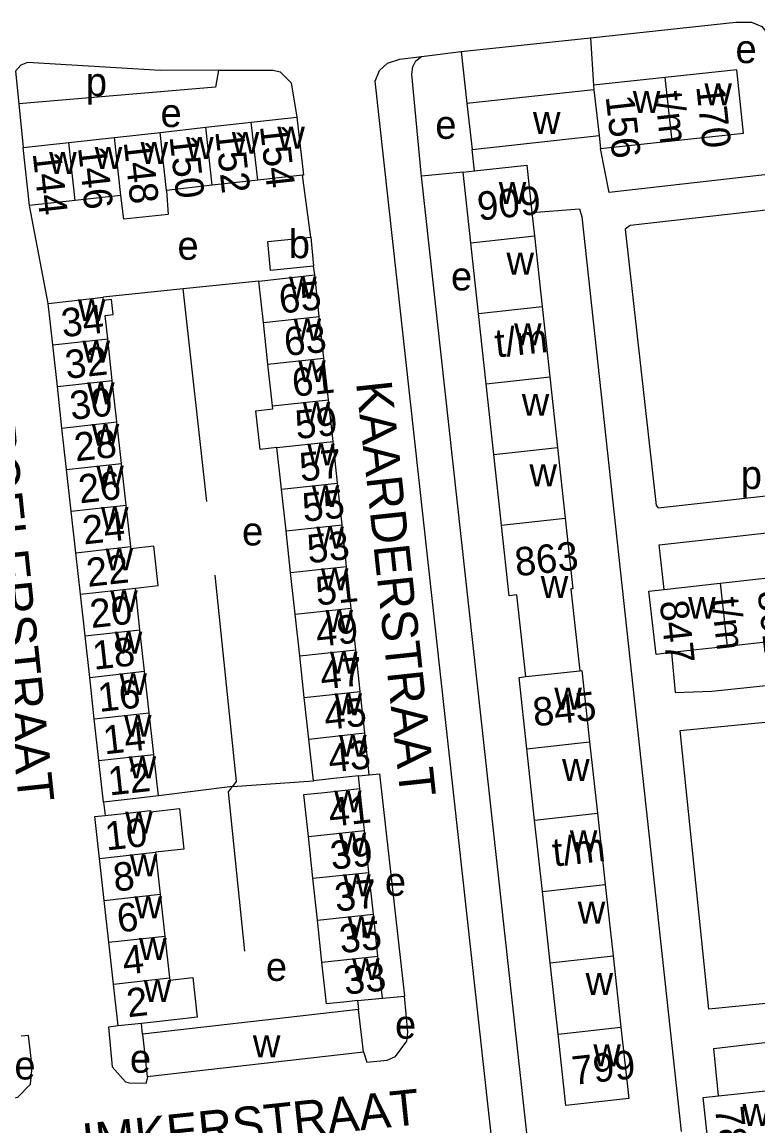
# Model space of a CAD drawing. Extents: x 159294 to 161936, y 384538 to 386517.
# Drawn here: x 161110.6 to 161214, y 385080.5 to 385235.4 of the extents above; entities that cross this region are included whole.
import ezdxf

# ---------------------------------------------------------------- set-up
doc = ezdxf.new("R2010")
doc.units = 0
for name, color, linetype in [('BLT_Basislijn', 7, 'Continuous'), ('BLT_Bebouwing', 7, 'Continuous'), ('BLT_Centroide', 7, 'Continuous'), ('BLT_Huisnummer', 7, 'Continuous'), ('BLT_Huisnummer_ tussenligend', 7, 'Continuous'), ('BLT_Huisnummer_reeks', 7, 'Continuous'), ('BLT_Onderverdeling_panden', 7, 'Continuous'), ('BLT_Straatnaam', 7, 'Continuous')]:
    doc.layers.add(name, color=color, linetype=linetype)

msp = doc.modelspace()

# ---------------------------------------------------------------- linework, layer by layer
at = {"layer": 'BLT_Basislijn'}
for p, q in [((161172.28, 385231.27), (161190.46, 385233.23)), ((161190.46, 385233.23), (161190.87, 385226.57)), ((161166.75, 385230.6), (161172.28, 385231.27)), ((161172.28, 385231.27), (161173.11, 385223.99)), ((161110.16, 385223.96), (161110.78, 385217.81)), ((161174.16, 385214.52), (161173.82, 385217.55)), ((161151.18, 385205.21), (161150.03, 385213.92)), ((161172.59, 385214.35), (161166.72, 385213.81)), ((161181.76, 385077.34), (161166.72, 385213.81)), ((161114.29, 385195.93), (161111.69, 385209.67)), ((161151.74, 385199.93), (161151.57, 385201.15)), ((161143.88, 385199.07), (161133.26, 385197.97)), ((161133.26, 385197.97), (161122.01, 385196.79)), ((161136.56, 385168.1), (161133.26, 385197.97)), ((161140.17, 385128.11), (161151.54, 385128.91)), ((161158.07, 385127.82), (161157.89, 385129.61)), ((161140.17, 385128.11), (161129.79, 385126.78)), ((161122.07, 385125.92), (161122.29, 385124.04)), ((161157.76, 385098.05), (161157.89, 385096.79)), ((161161.23, 385098.42), (161164.32, 385098.67)), ((161127.54, 385093.35), (161127.41, 385094.85))]:
    msp.add_line(p, q, dxfattribs=at)
for points in [[(161190.46, 385233.23), (161210.86, 385235.41), (161213.05, 385235.42), (161214.5, 385234.81), (161216.25, 385232.63)], [(161176.79, 385076.79), (161160.22, 385227.14), (161160.83, 385228.63), (161161.96, 385229.64), (161163.67, 385230.2), (161166.75, 385230.6)], [(161166.72, 385213.81), (161166.67, 385214.22), (161165.38, 385228.11), (161165.51, 385229.14), (161165.94, 385229.97), (161166.75, 385230.6)], [(161138.23, 385228.66), (161130.06, 385228.63), (161111.39, 385229.74), (161110.47, 385229.39), (161109.7, 385228.53), (161110.16, 385223.96)], [(161138.23, 385228.66), (161137.82, 385226.3), (161110.16, 385223.96)], [(161138.23, 385228.66), (161145.88, 385228.67), (161146.89, 385228.42), (161148.41, 385226.88), (161149.24, 385222.08)], [(161218.23, 385214.36), (161193.1, 385211.51), (161191.86, 385217.67)], [(161182.23, 385208.7), (161188.91, 385209.22), (161189.26, 385208.08), (161203.21, 385079.69)], [(161218.81, 385209.42), (161196.05, 385206.87), (161195.35, 385206.33), (161199.66, 385167.55), (161199.98, 385167.23), (161223.09, 385169.82)], [(161200.79, 385155.78), (161200.12, 385162.03), (161223.63, 385164.64)], [(161137.69, 385157.8), (161140.72, 385128.82), (161140.17, 385128.11)], [(161201.83, 385146.9), (161202.35, 385141.29), (161207.48, 385141.49), (161225.87, 385143.43)], [(161230.63, 385099.17), (161207.1, 385096.83), (161203.06, 385135.98), (161226.44, 385138.28)], [(161159.4, 385129.77), (161160.82, 385129.91), (161164.28, 385099.09), (161164.32, 385098.67)], [(161141.9, 385104.99), (161139.62, 385127.37), (161140.17, 385128.11)], [(161158.56, 385090.85), (161159.05, 385089.39), (161161.92, 385089.68), (161163.07, 385090.22), (161164.66, 385092.36), (161164.82, 385093.64), (161164.32, 385098.67)], [(161124.11, 385094.49), (161122.76, 385094.34), (161123.29, 385088.78), (161125.14, 385086.65), (161125.7, 385086.49), (161128.04, 385086.46), (161128.31, 385087.29), (161128.21, 385087.41)], [(161107.73, 385085.33), (161108.03, 385084.13), (161110.02, 385084.49), (161111.84, 385086.31), (161112.06, 385088.75), (161111.54, 385093.17), (161110.49, 385093.04)], [(161208.43, 385084.68), (161207.76, 385091.33), (161231.18, 385094.08)]]:
    msp.add_lwpolyline(points, dxfattribs=at)
at = {"layer": 'BLT_Bebouwing'}
for p, q in [((161200.95, 385227.65), (161190.87, 385226.57)), ((161190.94, 385225.92), (161173.11, 385223.99)), ((161190.87, 385226.57), (161190.94, 385225.92)), ((161173.11, 385223.99), (161173.82, 385217.55)), ((161136.42, 385220.65), (161142.83, 385221.36)), ((161142.83, 385221.36), (161149.24, 385222.08)), ((161123.6, 385219.23), (161130.01, 385219.94)), ((161130.01, 385219.94), (161136.42, 385220.65)), ((161110.78, 385217.81), (161117.19, 385218.52)), ((161117.19, 385218.52), (161123.6, 385219.23)), ((161173.82, 385217.55), (161191.66, 385219.48)), ((161191.66, 385219.48), (161191.86, 385217.67)), ((161191.86, 385217.67), (161201.91, 385218.76)), ((161111.69, 385209.67), (161110.78, 385217.81)), ((161150.03, 385213.92), (161143.74, 385213.22)), ((161172.59, 385214.35), (161174.16, 385214.52)), ((161173.66, 385204.44), (161172.59, 385214.35)), ((161137.33, 385212.51), (161130.92, 385211.8)), ((161143.74, 385213.22), (161137.33, 385212.51)), ((161124.51, 385211.09), (161118.1, 385210.38)), ((161118.1, 385210.38), (161111.69, 385209.67)), ((161182.23, 385208.7), (161182.58, 385205.41)), ((161151.18, 385205.21), (161151.57, 385201.15)), ((161174.74, 385194.53), (161173.66, 385204.44)), ((161182.58, 385205.41), (161183.66, 385195.5)), ((161152.38, 385194.09), (161151.74, 385199.93)), ((161144.52, 385193.23), (161143.88, 385199.07)), ((161114.94, 385190.1), (161114.29, 385195.93)), ((161183.66, 385195.5), (161184.74, 385185.6)), ((161153.02, 385188.24), (161152.38, 385194.09)), ((161175.82, 385184.63), (161174.74, 385194.53)), ((161145.16, 385187.38), (161144.52, 385193.23)), ((161123.31, 385185.12), (161122.66, 385190.96)), ((161115.59, 385184.26), (161114.94, 385190.1)), ((161145.8, 385181.54), (161145.16, 385187.38)), ((161153.66, 385182.39), (161153.02, 385188.24)), ((161116.24, 385178.43), (161115.59, 385184.26)), ((161123.95, 385179.29), (161123.31, 385185.12)), ((161176.9, 385174.72), (161175.82, 385184.63)), ((161184.74, 385185.6), (161185.81, 385175.69)), ((161154.3, 385176.55), (161153.66, 385182.39)), ((161116.89, 385172.6), (161116.24, 385178.43)), ((161124.6, 385173.45), (161123.95, 385179.29)), ((161154.93, 385170.7), (161154.3, 385176.55)), ((161147.07, 385169.84), (161146.43, 385175.69)), ((161185.81, 385175.69), (161186.89, 385165.78)), ((161125.25, 385167.62), (161124.6, 385173.45)), ((161177.98, 385164.81), (161176.9, 385174.72)), ((161117.53, 385166.76), (161116.89, 385172.6)), ((161155.57, 385164.86), (161154.93, 385170.7)), ((161147.71, 385164), (161147.07, 385169.84)), ((161125.9, 385161.79), (161125.25, 385167.62)), ((161118.18, 385160.93), (161117.53, 385166.76)), ((161148.35, 385158.15), (161147.71, 385164)), ((161156.21, 385159.01), (161155.57, 385164.86)), ((161118.83, 385155.09), (161118.18, 385160.93)), ((161148.99, 385152.3), (161148.35, 385158.15)), ((161156.85, 385153.16), (161156.21, 385159.01)), ((161200.79, 385155.78), (161208.68, 385156.67)), ((161119.48, 385149.26), (161118.83, 385155.09)), ((161127.19, 385150.12), (161126.55, 385155.95)), ((161181.37, 385143.53), (161180.11, 385155.02)), ((161187.72, 385155.84), (161187.69, 385155.83)), ((161187.69, 385155.83), (161188.97, 385144.36)), ((161157.49, 385147.32), (161156.85, 385153.16)), ((161149.62, 385146.46), (161148.99, 385152.3)), ((161127.84, 385144.28), (161127.19, 385150.12)), ((161120.13, 385143.43), (161119.48, 385149.26)), ((161158.12, 385141.47), (161157.49, 385147.32)), ((161209.67, 385147.78), (161201.83, 385146.9)), ((161150.26, 385140.61), (161149.62, 385146.46)), ((161128.49, 385138.45), (161127.84, 385144.28)), ((161189.23, 385144.39), (161190.33, 385134.38)), ((161120.77, 385137.59), (161120.13, 385143.43)), ((161158.76, 385135.63), (161158.12, 385141.47)), ((161150.9, 385134.77), (161150.26, 385140.61)), ((161121.42, 385131.76), (161120.77, 385137.59)), ((161129.14, 385132.61), (161128.49, 385138.45)), ((161151.54, 385128.91), (161150.9, 385134.77)), ((161159.4, 385129.77), (161158.76, 385135.63)), ((161182.61, 385123.4), (161181.51, 385133.41)), ((161190.33, 385134.38), (161191.42, 385124.37)), ((161122.07, 385125.92), (161121.42, 385131.76)), ((161129.79, 385126.78), (161129.14, 385132.61)), ((161157.89, 385129.61), (161159.4, 385129.77)), ((161158.7, 385121.94), (161158.07, 385127.82)), ((161191.42, 385124.37), (161192.52, 385114.35)), ((161183.71, 385113.39), (161182.61, 385123.4)), ((161151.47, 385115.22), (161150.84, 385121.09)), ((161159.34, 385116.06), (161158.7, 385121.94)), ((161122.16, 385112.12), (161121.51, 385118)), ((161129.39, 385118.87), (161130.04, 385112.99)), ((161159.97, 385110.18), (161159.34, 385116.06)), ((161152.1, 385109.34), (161151.47, 385115.22)), ((161192.52, 385114.35), (161193.62, 385104.34)), ((161130.04, 385112.99), (161130.69, 385107.12)), ((161184.81, 385103.37), (161183.71, 385113.39)), ((161122.81, 385106.25), (161122.16, 385112.12)), ((161160.6, 385104.3), (161159.97, 385110.18)), ((161152.73, 385103.46), (161152.1, 385109.34)), ((161130.69, 385107.12), (161131.34, 385101.24)), ((161123.46, 385100.37), (161122.81, 385106.25)), ((161161.23, 385098.42), (161160.6, 385104.3)), ((161193.62, 385104.34), (161194.72, 385094.33)), ((161185.91, 385093.36), (161184.81, 385103.37)), ((161124.11, 385094.49), (161123.46, 385100.37)), ((161157.76, 385098.05), (161161.23, 385098.42)), ((161157.89, 385096.79), (161127.54, 385093.35)), ((161158.56, 385090.85), (161157.89, 385096.79)), ((161127.41, 385094.85), (161124.11, 385094.49)), ((161127.54, 385093.35), (161128.21, 385087.41)), ((161128.21, 385087.41), (161158.56, 385090.85)), ((161208.43, 385084.68), (161216.36, 385085.55))]:
    msp.add_line(p, q, dxfattribs=at)
for points in [[(161201.91, 385218.76), (161211.96, 385219.84), (161211, 385228.74), (161200.95, 385227.65)], [(161149.24, 385222.08), (161150.14, 385213.93), (161150.03, 385213.92)], [(161174.16, 385214.52), (161181.51, 385215.33), (161182.23, 385208.7)], [(161130.92, 385211.8), (161131.15, 385208.43), (161124.93, 385207.74), (161124.51, 385211.09)], [(161151.57, 385201.15), (161145.54, 385200.56), (161145.14, 385204.63), (161151.18, 385205.21)], [(161143.88, 385199.07), (161146.77, 385199.39), (161151.74, 385199.93)], [(161114.29, 385195.93), (161119.26, 385196.48), (161122.01, 385196.79)], [(161122.66, 385190.96), (161122.29, 385194.23), (161123.43, 385194.36), (161123.19, 385196.48), (161122.06, 385196.35), (161122.01, 385196.79)], [(161146.43, 385175.69), (161144.07, 385175.41), (161143.47, 385180.86), (161145.84, 385181.11), (161145.8, 385181.54)], [(161186.89, 385165.78), (161187.99, 385155.87), (161187.72, 385155.84)], [(161180.11, 385155.02), (161179.06, 385154.9), (161177.98, 385164.81)], [(161126.55, 385155.95), (161129.76, 385156.34), (161129.15, 385161.83), (161125.93, 385161.47), (161125.9, 385161.79)], [(161208.68, 385156.67), (161218.69, 385157.79), (161219.68, 385148.9), (161209.67, 385147.78)], [(161201.83, 385146.9), (161199.66, 385146.66), (161198.67, 385155.54), (161200.79, 385155.78)], [(161188.97, 385144.36), (161189.23, 385144.39), (161189.23, 385144.39)], [(161181.51, 385133.41), (161180.42, 385143.43), (161181.37, 385143.53)], [(161157.89, 385129.61), (161154.43, 385129.23), (161151.54, 385128.91)], [(161129.79, 385126.78), (161127.04, 385126.48), (161122.07, 385125.92)], [(161150.84, 385121.09), (161150.21, 385126.97), (161153.1, 385127.28), (161158.07, 385127.82)], [(161121.51, 385118), (161120.86, 385123.88), (161122.29, 385124.04)], [(161122.29, 385124.04), (161125.83, 385124.43), (161128.67, 385124.74), (161128.69, 385124.55), (161132.74, 385125), (161133.03, 385122.36), (161133.36, 385119.31), (161129.39, 385118.87)], [(161157.76, 385098.05), (161156.26, 385097.89), (161153.37, 385097.58), (161152.73, 385103.46)], [(161131.34, 385101.24), (161131.37, 385100.92), (161134.62, 385101.28), (161135.24, 385095.72), (161131.99, 385095.36), (161129.08, 385095.04), (161127.41, 385094.85)], [(161194.72, 385094.33), (161195.82, 385084.31), (161187.01, 385083.35), (161185.91, 385093.36)], [(161209.42, 385075.65), (161207.27, 385075.41), (161206.28, 385084.45), (161208.43, 385084.68)]]:
    msp.add_lwpolyline(points, dxfattribs=at)
at = {"layer": 'BLT_Onderverdeling_panden'}
for p, q in [((161201.91, 385218.76), (161200.95, 385227.65)), ((161190.94, 385225.92), (161191.66, 385219.48)), ((161143.74, 385213.22), (161142.83, 385221.36)), ((161130.92, 385211.8), (161130.01, 385219.94)), ((161137.33, 385212.51), (161136.42, 385220.65)), ((161118.1, 385210.38), (161117.19, 385218.52)), ((161124.51, 385211.09), (161123.6, 385219.23)), ((161173.66, 385204.44), (161182.58, 385205.41)), ((161174.74, 385194.53), (161183.66, 385195.5)), ((161144.52, 385193.23), (161152.38, 385194.09)), ((161114.94, 385190.1), (161122.66, 385190.96)), ((161145.16, 385187.38), (161153.02, 385188.24)), ((161115.59, 385184.26), (161123.31, 385185.12)), ((161175.82, 385184.63), (161184.74, 385185.6)), ((161145.8, 385181.54), (161153.66, 385182.39)), ((161116.24, 385178.43), (161123.95, 385179.29)), ((161146.43, 385175.69), (161154.3, 385176.55)), ((161176.9, 385174.72), (161185.81, 385175.69)), ((161116.89, 385172.6), (161124.6, 385173.45)), ((161147.07, 385169.84), (161154.93, 385170.7)), ((161117.53, 385166.76), (161125.25, 385167.62)), ((161177.98, 385164.81), (161186.89, 385165.78)), ((161147.71, 385164), (161155.57, 385164.86)), ((161118.18, 385160.93), (161125.9, 385161.79)), ((161148.35, 385158.15), (161156.21, 385159.01)), ((161208.68, 385156.67), (161209.67, 385147.78)), ((161118.83, 385155.09), (161126.55, 385155.95)), ((161148.99, 385152.3), (161156.85, 385153.16)), ((161119.48, 385149.26), (161127.19, 385150.12)), ((161149.62, 385146.46), (161157.49, 385147.32)), ((161120.13, 385143.43), (161127.84, 385144.28)), ((161181.37, 385143.53), (161188.97, 385144.36)), ((161150.26, 385140.61), (161158.12, 385141.47)), ((161120.77, 385137.59), (161128.49, 385138.45)), ((161150.9, 385134.77), (161158.76, 385135.63)), ((161181.51, 385133.41), (161190.33, 385134.38)), ((161121.42, 385131.76), (161129.14, 385132.61)), ((161182.61, 385123.4), (161191.42, 385124.37)), ((161150.84, 385121.09), (161158.7, 385121.94)), ((161121.51, 385118), (161129.39, 385118.87)), ((161151.47, 385115.22), (161159.34, 385116.06)), ((161183.71, 385113.39), (161192.52, 385114.35)), ((161122.16, 385112.12), (161130.04, 385112.99)), ((161152.1, 385109.34), (161159.97, 385110.18)), ((161122.81, 385106.25), (161130.69, 385107.12)), ((161152.73, 385103.46), (161160.6, 385104.3)), ((161184.81, 385103.37), (161193.62, 385104.34)), ((161123.46, 385100.37), (161131.34, 385101.24)), ((161185.91, 385093.36), (161194.72, 385094.33))]:
    msp.add_line(p, q, dxfattribs=at)

# ---------------------------------------------------------------- texts
at = {"layer": 'BLT_Centroide'}
for s, p in [('e', (161210.82, 385229.66)), ('p', (161119.59, 385225.04)), ('w', (161206.46, 385223.75)), ('w', (161196.4, 385222.66)), ('e', (161130.08, 385220.68)), ('e', (161168.67, 385219.03)), ('w', (161182.38, 385219.72)), ('w', (161140.08, 385216.94)), ('w', (161146.48, 385217.66)), ('w', (161127.27, 385215.52)), ('w', (161133.67, 385216.22)), ('w', (161114.44, 385214.09)), ('w', (161120.84, 385214.81)), ('w', (161177.58, 385209.89)), ('b', (161148.09, 385202.28)), ('e', (161132.46, 385202.06)), ('w', (161178.66, 385199.97)), ('w', (161148.13, 385196.59)), ('e', (161170.87, 385197.75)), ('w', (161118.48, 385193.44)), ('w', (161148.77, 385190.72)), ('w', (161179.73, 385190.06)), ('w', (161119.12, 385187.62)), ('w', (161149.41, 385184.88)), ('w', (161119.77, 385181.78)), ('w', (161180.81, 385180.16)), ('w', (161150.04, 385179.03)), ('w', (161120.42, 385175.94)), ('w', (161150.68, 385173.19)), ('w', (161181.89, 385170.25)), ('w', (161121.06, 385170.09)), ('p', (161211.56, 385169.88)), ('w', (161151.32, 385167.34)), ('w', (161121.72, 385164.28)), ('e', (161141.53, 385161.95)), ('w', (161151.96, 385161.5)), ('w', (161122.36, 385158.44)), ('w', (161152.6, 385155.66)), ('w', (161183.47, 385154.58)), ('w', (161123.02, 385152.59)), ('w', (161204.17, 385151.66)), ('w', (161153.24, 385149.81)), ('w', (161123.66, 385146.78)), ('w', (161153.88, 385143.97)), ('w', (161124.31, 385140.94)), ('w', (161154.51, 385138.12)), ('w', (161185.38, 385138.91)), ('w', (161124.95, 385135.09)), ('w', (161155.15, 385132.28)), ('w', (161125.61, 385129.28)), ('w', (161186.47, 385128.89)), ('w', (161154.46, 385124.47)), ('w', (161125.11, 385121.5)), ('w', (161155.09, 385118.56)), ('w', (161187.56, 385118.88)), ('w', (161125.77, 385115.5)), ('e', (161161.58, 385112.76)), ('w', (161155.72, 385112.69)), ('w', (161126.42, 385109.62)), ('w', (161188.67, 385108.86)), ('w', (161156.35, 385106.81)), ('w', (161127.07, 385103.75)), ('e', (161144.87, 385100.82)), ('w', (161156.98, 385100.94)), ('w', (161127.72, 385097.88)), ('w', (161189.77, 385098.84)), ('e', (161163.01, 385092.71)), ('w', (161143.05, 385090.09)), ('w', (161190.86, 385088.84)), ('e', (161109.56, 385086.98)), ('e', (161125.78, 385087.93)), ('w', (161211.81, 385080.47))]:
    msp.add_text(s, height=4, dxfattribs=at).set_placement(p)
at = {"layer": 'BLT_Huisnummer'}
for s, rotation, p in [('154', 276.3286, (161144.03, 385220.83)), ('148', 276.3286, (161124.9, 385218.59)), ('144', 276.3278, (161112.12, 385217.01)), ('65', 6.1314, (161146.92, 385194.49)), ('34', 6.2948, (161116.36, 385191.17)), ('59', 6.1314, (161149.19, 385176.87)), ('28', 6.2948, (161118.17, 385173.74)), ('55', 6.1314, (161150.19, 385165.26)), ('24', 6.2948, (161119.33, 385162.08)), ('51', 6.1314, (161152.07, 385153.51)), ('20', 6.2948, (161120.38, 385150.34)), ('47', 6.1314, (161152.71, 385141.72)), ('16', 6.2948, (161121.49, 385138.57)), ('43', 6.1314, (161153.84, 385130.06)), ('12', 6.2948, (161122.92, 385126.84)), ('41', 6.1314, (161153.89, 385122.45)), ('10', 6.2948, (161122.49, 385119.12)), ('37', 6.1314, (161154.74, 385110.53)), ('6', 6.2948, (161124.18, 385107.6)), ('33', 6.1314, (161156.01, 385098.87)), ('2', 6.2948, (161125.52, 385095.71))]:
    msp.add_text(s, height=4, rotation=rotation, dxfattribs=at).set_placement(p)
at = {"layer": 'BLT_Huisnummer_ tussenligend'}
for s, rotation, p in [('152', 276.3286, (161137.76, 385220.08)), ('150', 276.3286, (161131.33, 385219.34)), ('146', 276.3278, (161118.48, 385217.82)), ('63', 6.1314, (161147.64, 385188.52)), ('32', 6.2948, (161116.89, 385185.32)), ('61', 6.1314, (161148.76, 385182.81)), ('30', 6.2948, (161117.56, 385179.56)), ('57', 6.1314, (161149.79, 385170.91)), ('26', 6.2948, (161118.77, 385167.85)), ('53', 6.1314, (161150.87, 385159.43)), ('22', 6.2948, (161119.88, 385156.13)), ('49', 6.1314, (161152.09, 385147.71)), ('18', 6.2948, (161120.74, 385144.49)), ('45', 6.1314, (161153.26, 385136.04)), ('14', 6.2948, (161122.23, 385132.61)), ('39', 6.1314, (161154.13, 385116.42)), ('8', 6.2948, (161123.65, 385113.35)), ('35', 6.1314, (161155.4, 385104.7)), ('4', 6.2948, (161124.96, 385101.67))]:
    msp.add_text(s, height=4, rotation=rotation, dxfattribs=at).set_placement(p)
at = {"layer": 'BLT_Huisnummer_reeks'}
for s, rotation, p in [('170', 276.1585, (161205.3, 385226.41)), ('156', 276.389, (161192.58, 385224.97)), ('t/m', 276.1585, (161199.48, 385225.53)), ('909', 6.2132, (161174.78, 385207.54)), ('t/m', 6.2181, (161177.24, 385188.32)), ('863', 6.2622, (161180.05, 385157.61)), ('t/m', 276.3912, (161207.43, 385154.46)), ('861', 276.3912, (161213.91, 385155.49)), ('847', 276.3912, (161200.17, 385154.06)), ('845', 6.2631, (161182.57, 385136.53)), ('t/m', 6.2638, (161185.32, 385116.86)), ('799', 6.256, (161188.06, 385086.21)), ('783', 276.2483, (161207.93, 385083.01))]:
    msp.add_text(s, height=4, rotation=rotation, dxfattribs=at).set_placement(p)
at = {"layer": 'BLT_Straatnaam'}
for s, height, rotation, p in [('KAARDERSTRAAT', 4.9999, 276.123, (161157.53, 385184.81)), ('SPOELERSTRAAT', 5, 275.9953, (161104.15, 385183.35)), ('IMKERSTRAAT', 5, 5.9759, (161119.36, 385075.77))]:
    msp.add_text(s, height=height, rotation=rotation, dxfattribs=at).set_placement(p)

doc.saveas('drawing.dxf')
